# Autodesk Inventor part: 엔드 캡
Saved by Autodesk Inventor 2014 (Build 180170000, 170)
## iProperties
Created: 2026-04
Part Number: 엔드 캡
Material: 일반
Document SubType Name: Modeling
Designer: dg
Density: 1 g/cm^3
Appearance: 기본값
Author: dg
Author: jhkim
Creation Date: 2026-03-27
Sending System: Autodesk Inventor 2026
Preprocessor: ST-DEVELOPER v20.1
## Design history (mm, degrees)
node "엔드 캡1"
node "솔리드1"
node "기준1"
